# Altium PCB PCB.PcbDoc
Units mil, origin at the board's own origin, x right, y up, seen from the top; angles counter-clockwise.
Board outline 3800 x 1700 mil, 2 copper layers (Top Layer, Bottom Layer), stack 62 mil thick; 48 components, 27 nets, 123 pads, 20 vias.
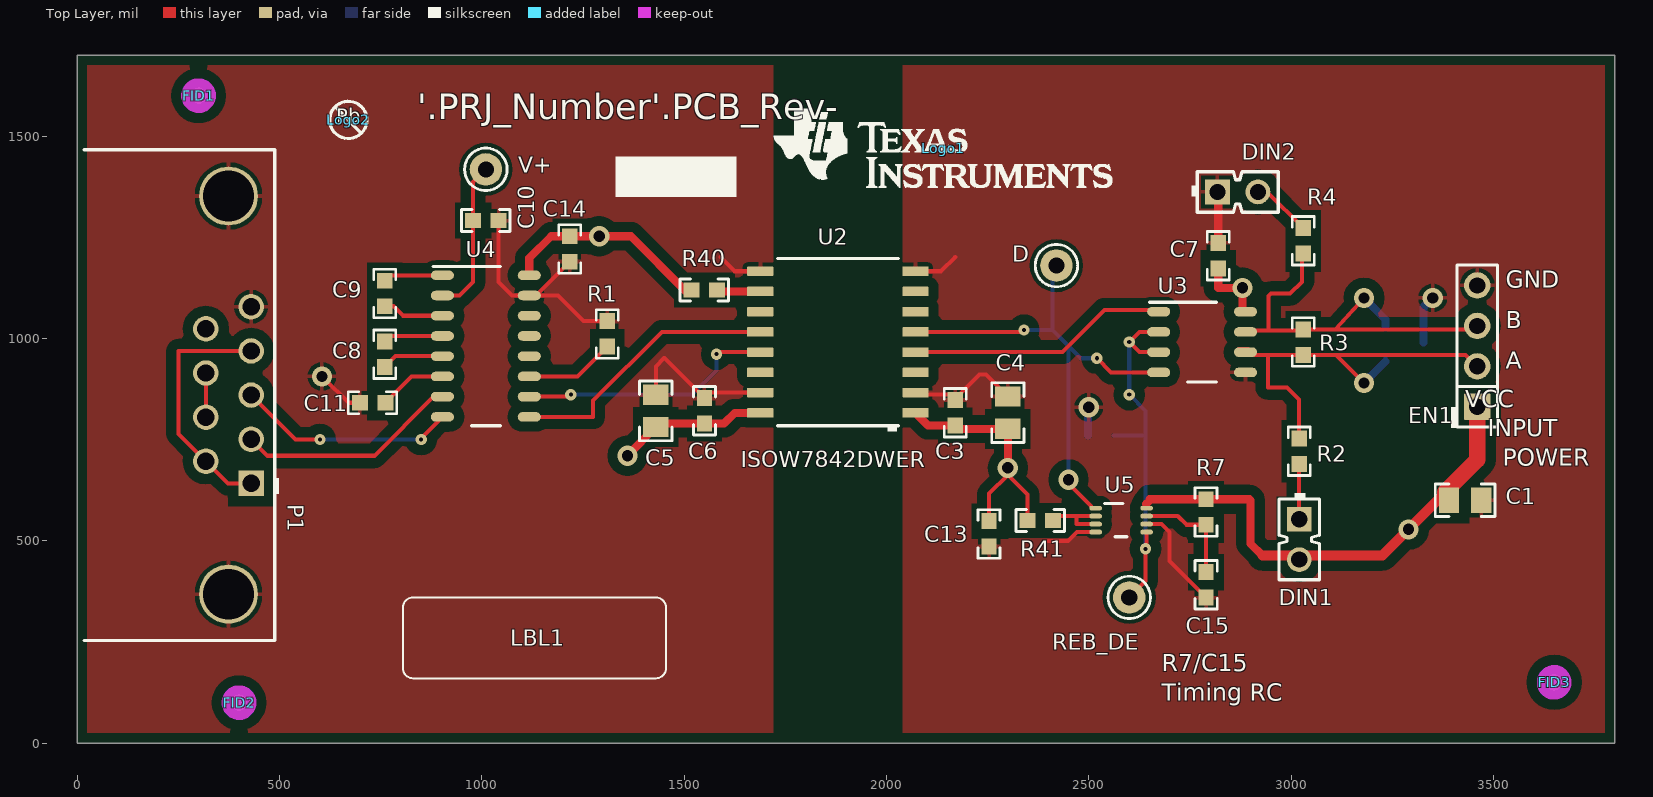
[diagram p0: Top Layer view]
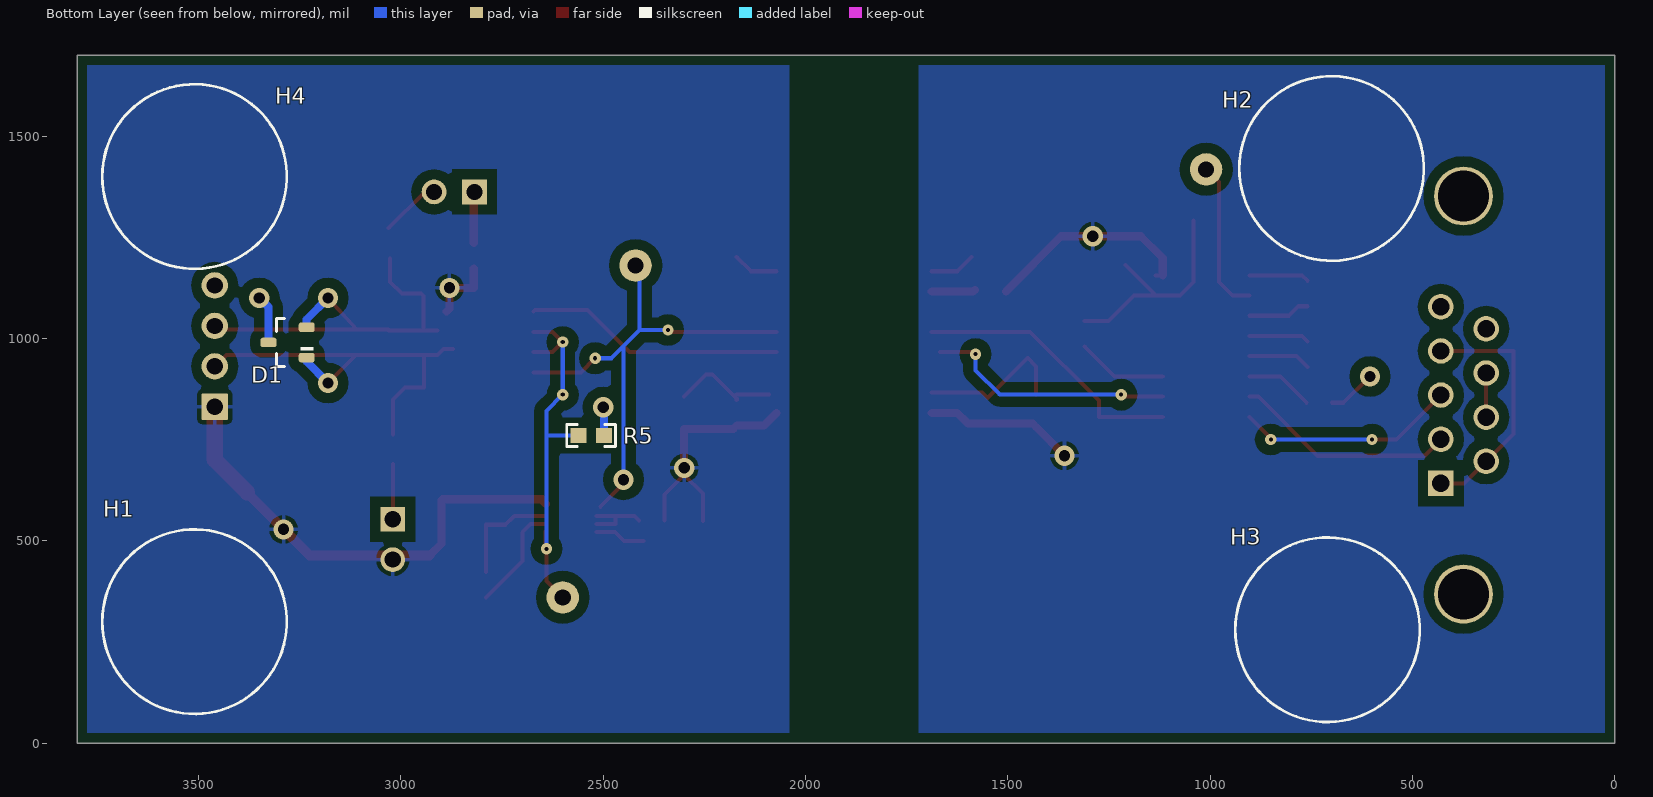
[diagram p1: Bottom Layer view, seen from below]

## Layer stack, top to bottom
Top Solder: solder mask 0.4, Solder Resist, Dk 3.5
Top Layer: signal copper 1.4
Dielectric1: core 59.2, FR-4, Dk 4.8
Bottom Layer: signal copper 1.4
Bottom Solder: solder mask 0.4, Solder Resist, Dk 3.5

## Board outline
0,0 3800,0 3800,1700 0,1700

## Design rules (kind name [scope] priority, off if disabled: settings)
AcuteAngle [All] p1: minimum=4.50000000000000E+0001 checktracksonly=FALSE
AssemblyTestPointUsage [All] p1: valid=2
BoardOutlineClearance BoardOutlineClearance_MountingHoles [OnCopper and InComponentClass('Mounting Holes')] p1: gap=40 ignorepadtopadclearanceinfootprint=FALSE
BoardOutlineClearance BoardOutlineClearance_Poly [OnCopper and IsPoly] p2: gap=25 ignorepadtopadclearanceinfootprint=FALSE
BoardOutlineClearance [OnCopper and Not InComponentClass('Logo') and not InComponentClass('FiducialMark') and not InRegion(1000,500,4000,800) and not InPoly] p3: gap=75 ignorepadtopadclearanceinfootprint=FALSE
Clearance Clearance_Keepouts [((IsTrack Or IsArc) And Not InPoly) And IsFree and IsKeepOut vs ((IsTrack Or IsArc) And Not InPoly) And IsFree and IsKeepOut] p1: gap=0 ignorepadtopadclearanceinfootprint=FALSE
Clearance Clearance_Poly [InPolygon] p2: gap=25 ignorepadtopadclearanceinfootprint=FALSE except(0: Arc-Hole Track-Hole SMDPad-Hole THPad-Hole Via-Hole Fill-Hole Poly-Hole Region-Hole Text-Hole)
Clearance Clearance_FiducialMark [IsKeepOut and InComponentClass('FiducialMark') vs IsPad and InComponentClass('FiducialMark')] p3: gap=0 ignorepadtopadclearanceinfootprint=FALSE
Clearance [All] p4: gap=7.87 ignorepadtopadclearanceinfootprint=FALSE except(0: Arc-Hole Track-Hole SMDPad-Hole THPad-Hole Via-Hole Fill-Hole Poly-Hole Region-Hole Text-Hole)
ComponentClearance ComponentClearance_MountingHoles_FiducialMarks [InComponentClass('Mounting Holes') vs InComponentClass('FiducialMark')] p1: gap=50 collisioncheckmode=3 verticalgap=10 showdistances=FALSE
ComponentClearance ComponentClearance_Shunt [InComponentClass('Header') vs InComponentClass('Shunt')] p2: gap=0 collisioncheckmode=3 verticalgap=0 showdistances=FALSE
ComponentClearance ComponentClearance_Logo [InComponentClass('Logo')] p3: gap=50 collisioncheckmode=3 verticalgap=10 showdistances=FALSE
ComponentClearance ComponentClearance_ScrewToNut [(HasFootprint('NY PMS 440 0025 PH')) vs (HasFootprint('Keystone_1902C'))] p4: gap=5 collisioncheckmode=3 verticalgap=10 showdistances=FALSE
ComponentClearance ComponentClearance_MountingHoles [InComponentClass('Mounting Holes')] p5: gap=250 collisioncheckmode=3 verticalgap=100000 showdistances=FALSE
ComponentClearance ComponentClearance_SmallPassives [HasFootprint('0201*') or HasFootprint('0402*') or HasFootprint('0508') or HasFootprint('0603*') or HasFootprint('0612') or HasFootprint('0805*') or HasFootprint('0815*') or HasFootprint('0830*') or HasFootprint('1206*') or HasFootprint('1210*') or HasFootprint('1808*') or HasFootprint('1812*') or HasFootprint('1825*') or HasFootprint('2010*') or HasFootprint('2220*') or HasFootprint('2225*') or HasFootprint('2512*') or HasFootprint('2728*') or HasFootprint('3518*') vs HasFootprint('0201*') or HasFootprint('0402*') or HasFootprint('0508') or HasFootprint('0603*') or HasFootprint('0612') or HasFootprint('0805*') or HasFootprint('0815*') or HasFootprint('0830*') or HasFootprint('1206*') or HasFootprint('1210*') or HasFootprint('1808*') or HasFootprint('1812*') or HasFootprint('1825*') or HasFootprint('2010*') or HasFootprint('2220*') or HasFootprint('2225*') or HasFootprint('2512*') or HasFootprint('2728*') or HasFootprint('3518*')] p6: gap=14.96 collisioncheckmode=3 verticalgap=10 showdistances=FALSE
ComponentClearance ComponentClearance_THtoSMT [IsThruComponent vs IsSMTComponent] p7: gap=40 collisioncheckmode=3 verticalgap=30 showdistances=FALSE
ComponentClearance ComponentClearance_THtoTH [IsThruComponent vs IsThruComponent] p8: gap=30 collisioncheckmode=3 verticalgap=30 showdistances=FALSE
ComponentClearance [All] p9: gap=30 collisioncheckmode=3 verticalgap=10 showdistances=FALSE
DiffPairsRouting [All] p1: maxlimit=100 minlimit=10 mostfreqgap=10 toplayer_minwidth=15 toplayer_maxwidth=15 toplayer_prefwidth=15 bottomlayer_minwidth=15 bottomlayer_maxwidth=15 bottomlayer_prefwidth=15 maxuncoupledlength=1000
FabricationTestPointUsage TestPointUsage [All] p1: valid=2 allowmultiple=FALSE
FabricationTestpoint Testpoint [All] p1: side=3 testpointundercomponent=TRUE minsize=40 maxsize=100 preferedsize=60 minholesize=0 maxholesize=40 preferedholesize=32 testpointgrid=1 allowsidetop=TRUE allowsidebottom=TRUE usegrid=TRUE gridtolerance=0.01
FanoutControl Fanout_LCC [IsLCC] p1: bgadir=Out bgaviamode=Centered fanoutstyle=Auto fanoutdirection=Alternating viagrid=1 // Fanout_LCC (Default Rule)
FanoutControl Fanout_BGA [IsBGA] p2: bgadir=Out bgaviamode=Centered fanoutstyle=Auto fanoutdirection=Alternating viagrid=1 // Fanout_BGA (Default Rule)
FanoutControl Fanout_Default [All] p4: bgadir=Out bgaviamode=Centered fanoutstyle=Auto fanoutdirection=Alternating viagrid=1 // Fanout_Default (Default Rule)
FanoutControl Fanout_Small [(CompPinCount < 5)] p5: bgadir=Out bgaviamode=Centered fanoutstyle=Auto fanoutdirection=OutThenIn viagrid=1 // Fanout_Small (Default Rule)
HoleSize [All] p1: absolutevalues=TRUE maxlimit=251 minlimit=7.87 maxpercent=80.000 minpercent=20.000
MinimumAnnularRing MinimumAnnularRing_ThermalPadVias [IsVia and InAnyComponent] p1: minimumring=5.91
MinimumAnnularRing [All] p2: minimumring=8
MinimumSolderMaskSliver MinimumSolderMaskSliver_Logo [InComponentClass('Logo') vs InComponentClass('Logo')] p1: minsoldermaskwidth=0.7
MinimumSolderMaskSliver [All] p2: minsoldermaskwidth=3.94
PlaneConnect [All] p1: planeconnectstyle=Relief reliefexpansion=10 reliefentries=4 reliefconductorwidth=10 reliefairgap=10
PolygonConnect [All] p1: connectstyle=Relief reliefconductorwidth=10 reliefentries=4 polygonreliefangle="90 Angle" airgapwidth=10
RoutingVias ThermalPadVias [IsVia and InAnyComponent] p1: holewidth=7.87 width=19.68 viastyle="Through Hole" minholewidth=7.87 minwidth=19.68 maxholewidth=12.99 maxwidth=23.62
RoutingVias [All] p2: holewidth=16 width=34 viastyle="Through Hole" minholewidth=7.87 minwidth=26 maxholewidth=40 maxwidth=65
SilkToBoardRegionClearance [Not ((IsComment or IsDesignator) And (Hide <> 'False')) and not InRegion(1000,500,4000,800)] p1:
SilkToSilkClearance SilkToSilkClearance_Pb-FreeLogo [(HasFootprint('Pb-Free_Overlay_Medium') OR HasFootprint('Pb-Free_Overlay_Small')) vs (HasFootprint('Pb-Free_Overlay_Medium') OR HasFootprint('Pb-Free_Overlay_Small'))] p1: silktosilkclearance=0
SilkToSilkClearance [All] p2: silktosilkclearance=4
SilkToSolderMaskClearance SilkToComponentPadClearance [(IsPad or IsFill or IsRegion) and InAnycomponent] p1: minsilkscreentomaskgap=5 clearancetoexposedcopper=TRUE
SilkToSolderMaskClearance "Silk to Solder Mask Opening" [All] p2: minsilkscreentomaskgap=4 clearancetoexposedcopper=FALSE
SolderMaskExpansion [All] p1: expansion=1.97
Width [All] p1: maxlimit=100 minlimit=6 preferedwidth=10 checkconnectedcopper=TRUE
15 further rules are at their usual default settings.

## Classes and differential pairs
component class Label: LBL1
component class AssemblyNote: ZZ1 ZZ2 ZZ3 ZZ4
component class FiducialMark: FID1 FID2 FID3
component class EVM_Hardware: FID1 FID2 FID3 H1 H2 H3 H4 LBL1 Logo1 Logo2 Logo3 ZZ1 ZZ2 ZZ3 ZZ4
component class Logo: Logo1
component class Header: DIN1 DIN2 EN1

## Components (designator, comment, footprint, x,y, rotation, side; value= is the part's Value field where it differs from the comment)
C1 "EMK212BJ106KG-T" 0805_HV 3430,600 r0 top value=10uF
C3 "GCM188R71C104KA37J" 0603 2170,816.59 r90 top value=0.1uF
C4 "GRM21BC80J106KE19L" 0805_HV 2300,816.59 r90 top value=10uF
C5 "GRM21BC80J106KE19L" 0805_HV 1430,821.04 r90 top value=10uF
C6 "GCM188R71C104KA37J" 0603 1550,821.04 r90 top value=0.1uF
C7 "GCM188R71C104KA37J" 0603 2820,1204.48 r90 top value=0.1uF
C8 "GCM188R71C104KA37J" 0603 760,961.04 r270 top value=0.1uF
C9 "GCM188R71C104KA37J" 0603 760,1111.04 r270 top value=0.1uF
C10 "GCM188R71C104KA37J" 0603 1010,1291.04 r0 top value=0.1uF
C11 "GCM188R71C104KA37J" 0603 730,841.04 r180 top value=0.1uF
C13 "GCM188R71C104KA37J" 0603 2253.7,516.81 r90 top value=0.1uF
C14 "GCM188R71C104KA37J" 0603 1217.36,1221.04 r270 top value=0.1uF
C15 "GRM188R70J224KA88D" 0603 2790,391.04 r270 top value=0.22uF
D "5000" Keystone5000 2420,1180 r90 top
D1 "SM712.TCT" SOT-23 3280,990 r0 bottom value="7V, 12V"
DIN1 "TSW-102-07-T-S" Samtec_TSW-102-07-T-S 3020,503.37 r270 top
DIN2 "TSW-102-07-T-S" Samtec_TSW-102-07-T-S 2867.99,1361.97 r0 top
EN1 "TSW-104-07-G-S" TSW-104-07-G-S 3460,981.04 r90 top
FID1 "Fiducial" Fiducial10-20 300,1600 r0 top
FID2 "Fiducial" Fiducial10-20 400,100 r0 top
FID3 "Fiducial" Fiducial10-20 3650,150 r0 top
H1 "SJ-5303 (CLEAR)" Bumpon_SJ5003Transparent 3510,300 r90 bottom
H2 "SJ-5303 (CLEAR)" Bumpon_SJ5003Transparent 700,1420 r180 bottom
H3 "SJ-5303 (CLEAR)" Bumpon_SJ5003Transparent 710,280 r90 bottom
H4 "SJ-5303 (CLEAR)" Bumpon_SJ5003Transparent 3510,1400 r90 bottom
LBL1 "THT-14-423-10" Label_650x200 1130,260 r0 top
Logo1 "Texas Instruments" TI_Stacked_Overlay_Small 2140,1470 r0 top
Logo2 "Pb-Free Symbol" Pb-Free_Overlay_Small 670,1540 r0 top
Logo3 "FCC disclaimer" FCC_disclaimer 2350,3380 r0 top
P1 "1734354-1" TE_1734354-1 0,860 r180 top
R1 "ERJ-3GEYJ472V" 0603 1310,1011.04 r90 top value=4.7k
R2 "ERJ-3GEYJ472V" 0603 3020,721.04 r270 top value=4.7k
R3 "CRCW0603120RJNEA" 0603 3030,991.04 r270 top value=120
R4 "ERJ-3GEYJ472V" 0603 3030,1241.04 r270 top value=4.7k
R5 "ERJ-3GEYJ472V" 0603 2530,760 r0 bottom value=4.7k
R7 "RMCF0603FT10K0" 0603 2790,571.04 r90 top value=10.0k
R40 "ERJ-3GEYJ472V" 0603 1550,1120 r180 top value=4.7k
R41 "ERJ-3GEYJ472V" 0603 2380,550 r180 top value=4.7k
REB_DE "5000" Keystone5000 2600,360 r90 top
U2 "ISOW7842DWER" DWE0016A 1880,991.04 r180 top
U3 "THVD1410D" D0008A_N 2780,991.04 r0 top
U4 "TRS3232EID" D0016A_N 1010,981.04 r0 top
U5 "SN74LVC1G123DCUR" DCU0008A_N 2580,551.04 r0 top
V+ "5000" Keystone5000 1010,1417.81 r90 top
ZZ1 "These assemblies must comply with workmanship standards IPC-A-610 Class 2, unless otherwise specified." AssemblyNote 185,3652 r0 top
ZZ2 "These assemblies must be clean and free from flux and all contaminants. Use of no clean flux is not acceptable." AssemblyNote 185,3740.56 r0 top
ZZ3 "These assemblies are ESD sensitive, ESD precautions shall be observed." AssemblyNote 185,3829.11 r0 top
ZZ4 "This Assembly Note is for PCB labels only" AssemblyNoteLabel 185,3938 r0 top

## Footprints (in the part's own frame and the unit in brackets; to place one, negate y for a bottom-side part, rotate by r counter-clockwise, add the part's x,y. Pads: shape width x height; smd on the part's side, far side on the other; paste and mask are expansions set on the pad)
0603 [mm] "0603 from SM-752 data"
  rect 1x0.95 smd: 1(-0.8,0) 2(0.8,0)
  silkscreen extent -1.52,-0.69 1.52,0.69, body extent -0.87,-0.47 0.87,0.47, height 1
0805_HV [mil] "0805 with 30mil clearance between pads"
  rect 50x63 smd: 1(-40,0) 2(40,0)
  silkscreen extent -74,-40 74,40, body extent -43,-29 43,29, height 57
AssemblyNote [mil] "Assembly Note"
AssemblyNoteLabel [mil] "Assembly Note for PCB Labels"
Bumpon_SJ5003Transparent [mil] "3M Hemispherical Bumpon transparent"
  round 1 on Mech4: 0(0,0)
  silkscreen extent -228,-228 228,228, body extent -219,-219 219,219, height 197
D0008A_N [mm] "SOIC, 8-Leads, Body 4.9x3.9mm, Pitch 1.27mm, IPC Medium Density"
  oval 1.45x0.6 smd: 1(-2.725,1.905) 2(-2.725,0.635) 3(-2.725,-0.635) 4(-2.725,-1.905) 5(2.725,-1.905) 6(2.725,-0.635) 7(2.725,0.635) 8(2.725,1.905)
  silkscreen extent -3.3,-2.5 0.9,2.5, body extent -3,-2.45 3,2.45, height 1.63
D0016A_N [mm] "SOIC, 16-Leads, Body 9.9x3.9mm, Pitch 1.27mm, IPC Medium Density"
  oval 1.45x0.6 smd: 1(-2.725,4.445) 2(-2.725,3.175) 3(-2.725,1.905) 4(-2.725,0.635) 5(-2.725,-0.635) 6(-2.725,-1.905) 7(-2.725,-3.175) 8(-2.725,-4.445) 9(2.725,-4.445) 10(2.725,-3.175) 11(2.725,-1.905) 12(2.725,-0.635) 13(2.725,0.635) 14(2.725,1.905) 15(2.725,3.175) 16(2.725,4.445)
  silkscreen extent -3.3,-5 0.9,5, body extent -3,-4.95 3,4.95, height 1.6
DCU0008A_N [mm] "TSSOP, 8-Leads, Body 2x2.3mm, Pitch 0.5mm, IPC Medium Density"
  oval 0.8x0.3 smd: 1(-1.6,0.75) 2(-1.6,0.25) 3(-1.6,-0.25) 4(-1.6,-0.75) 5(1.6,-0.75) 6(1.6,-0.25) 7(1.6,0.25) 8(1.6,0.75)
  silkscreen extent -1.05,-1.05 0.38,1.05, body extent -1.56,-1 1.56,1, height 0.9
DWE0016A [mm] "SOIC, 16-Leads, Body 10.5x7.6mm, Pitch 1.27mm"
  rrect17% 1.65x0.6 smd: 1(-4.875,4.445) 2(-4.875,3.175) 3(-4.875,1.905) 4(-4.875,0.635) 5(-4.875,-0.635) 6(-4.875,-1.905) 7(-4.875,-3.175) 8(-4.875,-4.445) 9(4.875,-4.445) 10(4.875,-3.175) 11(4.875,-1.905) 12(4.875,-0.635) 13(4.875,0.635) 14(4.875,1.905) 15(4.875,3.175) 16(4.875,4.445)
  silkscreen extent -3.8,-5.25 3.8,5.6, body extent -5.17,-5.15 5.17,5.15, height 2.59
FCC_disclaimer [mil]
Fiducial10-20 [mm]
  round 1 smd mask+0.5: 1(0,0)
  Top Layer keep-out circle w1.178: c0,0 r0.5
Keystone5000 [mil] "For Keystone 500x miniature loop terminals"
  round 80 hole 40: 1(0,0)
  silkscreen extent -52,-52 52,52, body extent -49,-49 49,49, height 182
Label_650x200 [mil] "Thermal Transfer Label"
  round 1 on Mech13: 0(0,0)
  silkscreen extent -325,-100 325,100, body extent -325,-100 325,100, height 1
Pb-Free_Overlay_Small [mil]
  silkscreen extent -46,-46 46,46
Samtec_TSW-102-07-T-S [mm] "Header, 2.54 mm, 2x1, Tin, TH"
  rect 1.55x1.55 hole 1.02: 1(-1.27,0)
  round 1.55 hole 1.02: 2(1.27,0)
  silkscreen extent -2.9,-1.27 2.54,1.27, body extent -2.54,-1.27 2.54,1.27, height 8.38
SOT-23 [mm] "SOT23, 3-Leads, Body 2.9x1.3mm, Pitch 0.95mm, Lead Span 2.5mm, IPC Medium Density"
  rrect50% 1x0.6 smd: 1(-1.2,0.95) 2(-1.2,-0.95) 3(1.2,0)
  silkscreen extent -1.62,-1.5 0.7,1.5, body extent -1.16,-1.45 1.21,1.45, height 1
TE_1734354-1 [mm] "Receptacle, D-Sub, 9 Position, R/A, TH"
  rect 1.6x1.6 hole 1.09: 1(-10.92,5.54)
  round 1.6 hole 1.09: 2(-10.92,2.77) 3(-10.92,0) 4(-10.92,-2.77) 5(-10.92,-5.54) 6(-8.08,4.155) 7(-8.08,1.385) 8(-8.08,-1.385) 9(-8.08,-4.155)
  round 3.7 hole 3.18: 10(-9.5,12.495) 11(-9.5,-12.495)
  silkscreen extent -12.68,-15.4 -0.43,15.4, body extent -12.4,-15.4 6.02,15.4, height 12.5
TI_Stacked_Overlay_Small [mil]
  silkscreen extent -418,-98 418,98
TSW-104-07-G-S [mm] "Samtec 100mil, 1x4, 230 mil above insulator"
  rrect6% 1.65x1.65 hole 1.016: 1(-3.81,0)
  round 1.65 hole 1.016: 2(-1.27,0) 3(1.27,0) 4(3.81,0)
  silkscreen extent -5.16,-1.27 5.08,1.65, body extent -5.08,-1.27 5.08,1.27, height 8.38

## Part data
C1: "CAP, CERM, 10 µF, 16 V,+/- 10%, X5R, 0805", Cap_Case=0805, Manufacturer="Taiyo Yuden", Supplier Part Number 1=587-1295-1-ND, TempCo=X5R, Tolerance_%=10, Value2=16V, ValueDisplayed=10µF
C3 C6 C7 C13: "CAP, CERM, 0.1 µF, 16 V,+/- 10%, X7R, AEC-Q200 Grade 1, 0603", Cap_Case=0603, Manufacturer=MuRata, Supplier Part Number 1=490-8015-1-ND, TempCo=X7R, Tolerance_%=10, Value2=16V, ValueDisplayed=0.1µF
C4 C5: "CAP, CERM, 10 µF, 6.3 V,+/- 10%, X6S, 0805", Cap_Case=0805, Manufacturer=MuRata, Supplier Part Number 1=GRM21BC80J106KE19L-ND, TempCo=X6S, Tolerance_%=10, Value2=6.3V, ValueDisplayed=10µF
C8 C9 C10 C11 C14: "CAP, CERM, 0.1 µF, 16 V, +/- 10%, X7R, AEC-Q200 Grade 1, 0603", Cap_Case=0603, Manufacturer=MuRata, Supplier Part Number 1=490-8015-1-ND, TempCo=X7R, Tolerance_%=10, Value1=Unknown, Value2=16V, ValueDisplayed=0.1µF
C15: "CAP, CERM, 0.22 µF, 6.3 V,+/- 10%, X7R, 0603", Cap_Case=0603, Manufacturer=MuRata, Supplier Part Number 1=GRM188R70J224KA88D-ND, TempCo=X7R, Tolerance_%=10, Value2=6.3V, ValueDisplayed=0.22µF
D REB_DE V+: "Test Point, Miniature, Red, TH", Color=Red, Manufacturer=Keystone, Supplier Part Number 1=36-5000-ND
D1: "Asymmetrical TVS Diode for Extended Common-Mode RS-485, SOT-23", Manufacturer=Semtech, Supplier Part Number 1=SM712CT-ND
DIN1 DIN2: "Header, 2.54 mm, 2x1, Tin, TH", Color=Black, Current_A=6.3, Manufacturer=Samtec, Supplier Part Number 1=SAM1035-02-ND, Voltage_V=550
EN1: "Header, 100mil, 4x1, Gold, TH", Color=Black, Current_A=6.3, Manufacturer=Samtec, Supplier Part Number 1=SAM1029-04-ND, Voltage_V=550
FID1 FID2 FID3: library part CMP-0077181-1, "Fiducial mark.  There is nothing to buy or mount.", Manufacturer=N/A
H1 H2 H3 H4: library part CMP-0003620-1, "Bumpon, Hemisphere, 0.44 X 0.20, Clear", Manufacturer=3M, Supplier Part Number 1=SJ5303-7-ND
LBL1: library part CMP-0003625-1, "Thermal Transfer Printable Labels, 0.650\" W x 0.200\" H - 10,000 per roll", Manufacturer=Brady, Supplier Part Number 1=97C5133
Logo1: library part CMP-0074838-1, "Texas Instrument Corporate Signature"
Logo2: library part CMP-0074839-1
Logo3: library part CMP-0074847-1, "FCC_disclaimer"
P1: "Receptacle, D-Sub, 9 Position, R/A, TH", Color=Black, Manufacturer="TE Connectivity", Supplier Part Number 1=A35107-ND
R1 R2 R4 R5 R40 R41: "RES, 4.7 k, 5%, 0.1 W, AEC-Q200 Grade 0, 0603", Manufacturer=Panasonic, Power_W=0.1, Supplier Part Number 1=P4.7KGCT-ND, TempCo="200 ppm/C", Tolerance_%=5, Value1=5%, Value2=0.1W, Value_Code=4k70, ValueDisplayed=4.7k
R3: "RES, 120, 5%, 0.1 W, 0603", Manufacturer=Vishay-Dale, Power_W=0.1, Supplier Part Number 1=541-120GCT-ND, TempCo="200 ppm/C", Tolerance_%=5, Value1=5%, Value2=0.1W, Value_Code=120R, ValueDisplayed=120
R7: "RES, 10.0 k, 1%, 0.1 W, AEC-Q200 Grade 0, 0603", Manufacturer="Stackpole Electronics Inc", Power_W=0.1, Supplier Part Number 1=RMCF0603FT10K0CT-ND, TempCo="100 ppm/C", Tolerance_%=1, Value1=1%, Value2=0.1W, Value_Code=10k0, ValueDisplayed=10.0k
U2: "High-Performance, 5000-VRMS Reinforced Quad-Channel Digital Isolators With Integrated High-Efficiency, Low-Emissions DC-DC Converter, DWE0016A (SOIC-16)", Alternate Manufacturer="Texas Instruments", Alternate PartNumber=ISOW7842DWE
U3: library part CMP-0065060-3, "3.3-V to 5-V RS-485 Transceivers With +/-18-kV IEC ESD Protection, D0008A (SOIC-8)", Alternate Manufacturer="Texas Instruments", Alternate PartNumber=THVD1410DR, Operating Temperature Range="-40 to 125 C"
U4: "3-V to 5.5-V Multichannel RS-232 Line Driver / Receiver with ±15-kV IEC ESD Protection, -40 to 85 degC, 16-Pin SOIC (D), Green (RoHS & no Sb/Br)", Alternate Manufacturer="Texas Instruments", Alternate PartNumber=Equivalent, Drivers Per Package=2, Supplier Part Number 1=TRS3232EID-ND, Supply Voltage(s)(V)="3.3 or 5.0"
U5: "Single Retriggerable Monostable Multivibrator with Schmitt-Trigger Inputs, DCU0008A, LARGE T&R", Alternate Manufacturer="Texas Instruments", Alternate PartNumber=Equivalent, F @ Nom Voltage(Max)(Mhz)=150, Generic Part Number=SN74LVC1G123, ICC @ Nom Voltage(Max)(mA)=0.02, Operating Temperature Range(C)="-40 to 125,-40 to 85", Rating=Catalog, Supplier Part Number 1=595-SN74LVC1G123DCUR, tpd @ Nom Voltage(Max)(ns)=34,11,8,5.5, Voltage(Nom)(V)=1.8,2.5,3.3,5
ZZ1: library part CMP-0077238-1
ZZ2: library part CMP-0077237-1
ZZ3: library part CMP-0077236-1
ZZ4: library part CMP-0003616-3

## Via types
v1: diameter 50, hole 28, Top Layer to Bottom Layer, 11 vias
v2: diameter 28, hole 10, Top Layer to Bottom Layer, 9 vias

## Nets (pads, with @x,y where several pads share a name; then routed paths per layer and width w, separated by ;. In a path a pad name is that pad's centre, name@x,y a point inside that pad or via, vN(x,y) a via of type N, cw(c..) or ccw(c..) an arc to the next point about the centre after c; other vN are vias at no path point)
A: D1.1 EN1.2 R2.1 R3.2 U3.6 | length 1047.2
  Top Layer w10: U3.6@2871.46,974.38 2894.32,974.38 2909.16,959.54 2944.21,959.54 ; R2.1@3020,762.53 3020,848.7 2990,878.7 2942.34,878.7 2942.34,957.67 2944.21,959.54 ; v1(3180,890) 3110.46,959.54 ; EN1.2 3431.5,959.54 3110.46,959.54 ; 2944.21,959.54 R3.2 3110.46,959.54
  Bottom Layer w10: D1.1@3232.76,942.76 D1.1
  Bottom Layer w20: v1(3180,890) D1.1@3232.76,942.76
B: D1.2 EN1.3 R3.1 R4.2 U3.7 | length 1000.2
  Top Layer w10: U3.7@2909.16,1019.54 2944.21,1019.54 ; R4.2@3026.51,1197.04 3026.51,1139.88 2997.66,1111.04 2950,1111.04 2944.21,1105.25 2944.21,1019.54 ; R3.1@3030,1019.54 2944.21,1019.54 ; R3.1 3110,1022.53 ; v1@3180,1092.53 v1(3180,1100) 3110,1022.53 ; EN1.3 3451.5,1022.53 3110,1022.53
  Bottom Layer w20: v1(3180,1100) 3232.76,1047.24 D1.2
D: D.1 U2.5 U3.4 U5.1 | length 1222.4
  Top Layer w10: U2.5 2335,1016.04 v2(2340,1021) ; v1@2450,641.04 U5.1@2507.01,584.03 ; v2@2521.61,952.65 v2(2520,951.04) 2555,916.04 U3.4
  Bottom Layer w10: v2(2340,1021) 2410,1021.04 ; D.1 2410,1170 2410,1021.04 ; v1(2450,651) 2450,981.04 ; v2(2520,951.04) 2480,951.04 2450,981.04 ; 2410,1021.04 2450,981.04
DIN: U2.13 U4.10 | length 619.8
  Top Layer w10: U4.10 1215,856.04 v2(1220,861.04) ; v2(1580,961.04) 1585,966.04 U2.13@1668.07,966.04
  Bottom Layer w10: v2(1220,861.04) 1520,861.04 1580,921.04 v2(1580,961.04)
GND: C5.2 C6.2 C10.2 C11.2 C14.2 P1.5 P1.10 P1.11 R1.2 U2.9 U2.15 U4.15 | length 1174.9
  Top Layer w10: v1@610,901.04 670,841.04 C11.2 ; C10.2 1041.5,1139.54 1075,1106.04 U4.15 U4.15@1133.86,1106.04 ; C14.2@1208.86,1181.04 U4.15@1133.86,1106.04 ; R1.2 1251.5,1042.53 1230,1064.03 1187.99,1106.04 U4.15@1133.86,1106.04 ; C5.2 1430,931.04 1450,951.04 1451.5,951.04 C6.2 1563.5,866.04 U2.15 ; 1590,1201.04 1625,1166.04 U2.9
  other v1: 605,906.04
GND_SIGNAL: C1.2 C3.2 C4.2 C7.2 C13.1 C15.2 D1.3 DIN2.1 EN1.4 R5.1 U2.2 U2.8 U3.5 U5.4 U5.6 | length 1080.2
  Top Layer w10: U2.8 2135,1166.04 2170,1201.04 ; U2.2@2090,861.04 C3.2@2170.12,861.04 ; C3.2 2170,851.04 2230,911.04 2245.55,911.04 C4.2 ; 2400,499.54 2448.5,499.54 2470.47,521.51 U5.4 ; U5.6 2679.84,541.2 2700,521.04 2700,449.54 C15.2
  Top Layer w20: DIN2.1 2820,1359.97 C7.2
  Bottom Layer w20: R5.1 2498.5,828.5 v1(2500,830) ; D1.3 3327.24,1077.24 v1(3350,1100)
NetC8_1: C8.1 U4.4 | length 148.3
  Top Layer w10: C8.1 773.5,1006.04 U4.4
NetC8_2: C8.2 U4.5 | length 153.7
  Top Layer w10: C8.2 786.5,956.04 U4.5
NetC9_1: C9.1 U4.1 | length 148.3
  Top Layer w10: C9.1 773.5,1156.04 U4.1
NetC9_2: C9.2 U4.3 | length 152.5
  Top Layer w10: C9.2 781.5,1079.54 805,1056.04 U4.3
NetC10_1: C10.1 U4.2 V+.1 | length 381
  Top Layer w10: U4.2 945,1106.04 978.5,1139.54 C10.1 978.5,1386.32 V+.1
NetC11_1: C11.1 U4.6 | length 168.1
  Top Layer w10: C11.1 826.5,906.04 U4.6
NetC15_1: C15.1 R7.1 U5.7 | length 272.9
  Top Layer w10: U5.7 2719.84,560.88 2741.18,539.54 R7.1 C15.1
NetDIN1_1: DIN1.1 R2.2 | length 126
  Top Layer w10: DIN1.1@3020,563.55 R2.2
NetDIN2_2: DIN2.2 R4.1 | length 149.1
  Top Layer w10: DIN2.2 2940.56,1361.97 R4.1
NetP1_1: P1.1 P1.4 P1.6 | length 613.8
  Top Layer w10: P1.1 372.64,641.89 P1.6 250.94,763.58 250.94,969.06 P1.4
NetP1_7: P1.7 P1.8 | length 109.1
  Top Layer w10: P1.7 P1.8
NetR1_1: R1.1 U4.11 | length 223.2
  Top Layer w10: U4.11 1236.5,906.04 R1.1
NetR40_1: R40.1 U2.10 | length 108.2
  Top Layer w20: R40.1 1585.46,1116.04 U2.10
NetR41_1: R41.1 U5.2 U5.3 | length 177.2
  Top Layer w10: R41.1 2422.38,560.88 2470,560.88 ; U5.3 2469.69,541.2 2470,541.51 2470,560.88 ; U5.2 2470,560.88
R: U2.4 U3.1 | length 645.5
  Top Layer w10: U2.4 2435,966.04 2538.96,1070 2668.75,1070 U3.1
RD: P1.3 U4.8 | length 520.7
  Top Layer w10: P1.3 529.92,760 530,760 540,750 v2@590,750 ; v2@856.68,760 U4.8
  Bottom Layer w10: v2(600,750) 840,750 v2(850,750)
REB_DE: R5.2 REB_DE.1 U3.2 U3.3 U5.5 | length 952.9
  Top Layer w10: REB_DE.1 2640,400 v2(2640,480) 2642.99,482.99 U5.5 U5.5@2642.09,522.42 ; U3.3 2625,966.04 v2(2600,991.04) 2625,1016.04 U3.2
  Bottom Layer w10: R5.2 2640,760 ; v2(2600,991.04) v2(2600,861.04) 2640,821.04 2640,760 ; v2(2640,480) 2640,760
ROUT: U2.12 U4.9 | length 681.2
  Top Layer w10: U4.9 1275,806.04 1275,846.04 1445,1016.04 U2.12
TD: P1.2 U4.7 | length 550.2
  Top Layer w10: P1.2 470.87,710 735.04,710 881.08,856.04 U4.7
VCC: C1.1 C3.1 C4.1 C7.1 C13.2 DIN1.2 EN1.1 R7.2 R41.2 U2.1 U3.8 U5.8 | length 1965
  Top Layer w10: C3.1 C3.1@2178.5,776.59 ; C13.2 2253.7,616.23 v1@2300,662.53 ; v1@2300,700 v1(2300,680) v1@2300,662.53 ; R41.2 2348.5,614.03 v1@2300,662.53
  Top Layer w20: U2.1 2102.87,785.09 C3.1 ; C3.1@2178.5,776.59 C4.1 v1@2300,700 ; 2641.47,590.41 2648.79,597.74 ; 2650.31,602.53 R7.2 2897.47,602.53 2900,600 2900,492.53 2928.99,463.55 ; C7.1 2820,1124.88 v1(2880,1124.88) 2880,1073.32 U3.8 ; C1.1@3380,618.22 C1.1@3380,620
  Top Layer w25: 2928.99,463.55 3225.32,463.55 C1.1@3380,618.22
  Top Layer w40: C1.1@3380,620 3460,700 EN1.1
  other v1: 3290,528
VSIO: C5.1 C6.1 C14.1 R40.2 U2.16 U4.16 | length 887.3
  Top Layer w10: U4.16 U4.16@1135,1156.04 ; v1(1360,710) v1@1360,711.04
  Top Layer w20: U4.16 1117.28,1198.32 1171.5,1252.53 C14.1 1368.5,1252.53 R40.2@1505,1116.04 ; v1@1360,711.04 C5.1 ; C5.1@1438.5,789.54 C6.1 1598.5,789.54 1625,816.04 U2.16
  other v1: 1290,1252.53
pads on no net: FID1.1 FID2.1 FID3.1 H1.0 H2.0 H3.0 H4.0 LBL1.0 P1.9 U2.3 U2.6 U2.7 U2.11 U2.14 U4.12 U4.13 U4.14

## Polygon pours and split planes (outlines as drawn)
GND_SIGNAL on Top Layer "TOP_LAYER_GND_SIGNAL_P006" (solid, remove dead copper, pour order 6): 2040,0 2040,1700 3800,1700 3800,0
GND on Top Layer "TOP_LAYER_GND_P004" (solid, remove dead copper, pour order 4): 0,1690 10,1700 1720,1700 1720,0 0,0
VSIO on Bottom Layer "BOTTOM_LAYER_VSIO_P008" (solid, remove dead copper, pour order 8): 0,0 0,1700 1720,1700 1720,0
VCC on Bottom Layer "BOTTOM_LAYER_VCC_P010" (solid, remove dead copper, pour order 10): 2040,0 2040,1700 3800,1700 3800,0

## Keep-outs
Keep-Out Layer:
  text ".Layer_Name" at 577,-858.49 h60

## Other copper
Top Layer:
  text ".Layer_Name" at 577,-858.49 h60
Bottom Layer:
  text ".Layer_Name" at 577,-858.49 h60

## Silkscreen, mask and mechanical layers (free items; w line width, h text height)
Top Overlay:
  region: 1630,1450 1330,1450 1330,1350 1630,1350
  text "'.PRJ_Number'.PCB_Rev-" at 840,1520 h108.27
  text "GND" at 3530,1110 h72.83
  text "B" at 3530,1010 h72.83
  text "A" at 3530,910 h72.83
  text "VCC /    INPUT /      POWER" at 3430,670 h72.83
  text "R7/C15 / Timing RC" at 2680,90 h72.83
  text ".Layer_Name" at 577,-858.49 h60
Bottom Overlay:
  text ".Layer_Name" at 577,-858.49 h60
Top Paste:
  text ".Layer_Name" at 577,-858.49 h60
Bottom Paste:
  text ".Layer_Name" at 577,-858.49 h60
Top Solder:
  text ".Layer_Name" at 577,-858.49 h60
  text ".Layer_Name" at 577,-858.49 h60
Bottom Solder:
  text ".Layer_Name" at 577,-858.49 h60
Drill Guide:
  text ".Layer_Name" at 577,-858.49 h60
M1 Board Outline:
  the board outline again, w10
  text ".Layer_Name" at 577,-858.49 h60
M2 Board Dimensions:
  rectangle: 125,-400 500,-275
  rectangle: 0,-275 125,-150
  lines w7: 0,-275 1000,-275 ; 125,-400 125,-150 ; 250,-400 250,-150 ; 500,-400 500,-150 ; 750,-400 750,-150 ; 0,-400 0,-150 1000,-150 1000,-400 0,-400
  lines w10: -120,60 -100,0 ; -120,1640 -100,1700 ; -110,0 -90,0 ; -110,1700 -90,1700 ; -100,574.08 -100,0 ; -100,1125.92 -100,1700 ; -80,60 -100,0 ; -80,1640 -100,1700
  text "1700 (mil)" at -64.01,584.08 h60 r90
  text ".Layer_Name" at 577,-858.49 h60
M3 3D STEP Top:
  text ".Layer_Name" at 577,-858.49 h60
M4 3D STEP Bottom:
  text ".Layer_Name" at 577,-858.49 h60
M5 Assembly Top:
  lines w10: -292,-930.17 6308,-930.17 ; -292,-726.83 6310,-726.83 ; -292,-523.5 -292,-1133.5 3713,-1133.5 6310,-1133.5 6310,-523.5 -291.5,-523.5 -291.5,-1133.5 1284,-1133.5 ; 2173,-1133.5 2173,-523.5 ; 3440,-726.83 3440,-523.5 ; 4280,-726.83 4280,-523.5 ; 4902,-1140 4902,-937.17
  text "COMPONENTS MARKED 'DNP' SHOULD NOT BE POPULATED." at 1153.5,-318.5 h60
  text "ASSEMBLY VARIANT:" at 1153,-434 h60
  text ".VariantName" at 2189,-434 h60
  text "PCB VIEWED FROM TOP SIDE" at -228.5,-655.67 h60
  text "BOARD #:" at 2248,-655.67 h60
  text ".PRJ_Number" at 2793.5,-655.67 h60
  text "REV:" at 3638,-655.67 h60
  text ".PCB_Rev" at 3929.5,-655.67 h60
  text "SVN REV:" at 4476,-655.67 h60
  text ".VersionControl_RevNumber" at 4982,-655.67 h60
  text "TID #:" at 2248,-859 h60
  text ".TID" at 2793.5,-859 h60
  text "PLOT NAME =" at -228.5,-1064.34 h60
  text ".plot_File_Name" at 577,-1064.34 h60
  text "GENERATED    :" at 2250,-1064.34 h60
  text ".Print_Date" at 3119.5,-1064.34 h60
  text ".Print_Time" at 3848.5,-1064.34 h60
  text "TEXAS INSTRUMENTS" at 5113,-1064.34 h60
M6 Assembly Bottom:
  lines w10: -292.5,-727.33 6309.5,-727.33 ; -290.5,-930.67 6309.5,-930.67 ; 1115.5,-1140.5 1115.5,-937.67 ; 1737.5,-727.33 1737.5,-524 ; 2577.5,-727.33 2577.5,-524 ; 3844.5,-1134 3844.5,-524 ; 4733.5,-1134 6309,-1134 6309,-524 -292.5,-524 -292.5,-1134 2304.5,-1134 6309.5,-1134 6309.5,-524
  text "COMPONENTS MARKED 'DNP' SHOULD NOT BE POPULATED." at 6102,-318 h60
  text ".VariantName" at 5058,-434 h60
  text "ASSEMBLY VARIANT:" at 6097,-434 h60
  text ".VersionControl_RevNumber" at 1035.5,-656.17 h60
  text "SVN REV:" at 1541.5,-656.17 h60
  text ".PCB_Rev" at 2088,-656.17 h60
  text "REV:" at 2379.5,-656.17 h60
  text ".PRJ_Number" at 3224,-656.17 h60
  text "BOARD #:" at 3769.5,-656.17 h60
  text "PCB VIEWED FROM BOTTOM SIDE" at 6246,-656.17 h60
  text ".TID" at 3224,-859.5 h60
  text "TID #:" at 3769.5,-859.5 h60
  text "TEXAS INSTRUMENTS" at 904.5,-1064.84 h60
  text ".Print_Time" at 2169,-1064.84 h60
  text ".Print_Date" at 2898,-1064.84 h60
  text "GENERATED    :" at 3767.5,-1064.84 h60
  text ".plot_File_Name" at 5440.5,-1064.84 h60
  text "PLOT NAME =" at 6246,-1064.84 h60
M9 Title Sheet:
  drawing of 57 lines, arcs and shapes, not listed
  text "1" at 739.84,8036.5 h70
  text "2" at 3235.5,8036.5 h70
  text "3" at 5724.84,8036.5 h70
  text "4" at 8231.51,8036.5 h70
  text "5" at 10730.5,8036.5 h70
  text "6" at 13235.5,8036.5 h70
  text "A" at -416.5,6893.5 h70
  text "A" at 14383.5,6893.5 h70
  text "B" at -416.5,4513.5 h70
  text "B" at 14383.5,4513.5 h70
  text "C" at -416.5,2138.5 h70
  text "C" at 14383.5,2138.5 h70
  text "PROJECT TITLE:" at 11343.5,277.5 h45
  text ".PRJ_Title" at 11393.5,144.17 h70
  text "DESIGNED FOR:" at 11343.5,-23.5 h45
  text ".PRJ_Customer" at 11393.5,-163.5 h70
  text "D" at -416.5,-231.5 h70
  text "D" at 14383.5,-231.5 h70
  text "FILE NAME:" at 11343.5,-323.5 h45
  text ".PCB_File_Name_No_Path" at 11393.5,-443.5 h70
  text "Texas Instruments (TI) and/or its licensors do not warrant the accuracy or completeness of this specification" at 6374,-605.34 h45
  text "ENGINEER:" at 11343.5,-613.5 h45
  text "LAYOUT BY:" at 12848.5,-613.5 h45
  text "or any information contained therein. TI and/or its licensors do not warrant that this design will meet" at 6329.01,-718 h45
  text ".PRJ_Engineer" at 11393.5,-768.49 h70
  text ".PCB_Layout" at 12899,-768.49 h70
  text "the specifications, will be suitable for your application or fit for any particular purpose, or will operate in" at 6329.01,-830.67 h45
  text ".Layer_Name" at 577,-858.49 h60
  text "ALTIUM DESIGNER VERSION:" at 12848.5,-923.5 h45
  text "an implementation. TI and/or its licensors do not warrant that the design is production worthy. You should" at 6329.01,-943.33 h45
  text "completely validate and test your design implementation to confirm the system functionality for your application." at 6374,-1056 h45
  text ".print_Scale" at 11393.5,-1056.83 h70
  text ".Application_BuildNumber" at 12899,-1056.83 h70
  text "1" at 739.84,-1263.5 h70
  text "2" at 3235.5,-1263.5 h70
  text "3" at 5724.84,-1263.5 h70
  text "4" at 8231.51,-1263.5 h70
  text "5" at 10730.5,-1263.5 h70
  text "6" at 13235.5,-1263.5 h70
M10 Fab Notes:
  drawing of 189 lines, arcs and shapes, not listed
  text "DESIGN INFORMATION" at 12382.02,6356.17 h60
  text "MIN. TRACK WIDTH:" at 11737.46,6224.05 h60
  text "8" at 12833.7,6224.05 h60
  text "MIL" at 12988.46,6224.05 h60
  text "MIN. CLEARANCE:" at 11737.46,6099.92 h60
  text "0.2" at 12773.7,6099.93 h60
  text "mm" at 12988.46,6099.92 h60
  text "MIN. VIA PAD SIZE:" at 11737.46,5975.8 h60
  text "24" at 12803.71,5975.8 h60
  text "MIL" at 12988.46,5975.8 h60
  text "0.05mm (2MIL)" at 12432.46,5845.9 h60
  text "MINIMUM ANNULAR RING" at 11408.23,5837.67 h60
  text "EXTERNAL" at 13140.46,5837.67 h60
  text "PER" at 11608.23,5727.55 h60
  text "IPC-D-275 CLASS 2 LEVEL C" at 11828.23,5727.54 h60
  text "MIL, HOLES" at 13316.46,5627.07 h60
  text "+/-" at 12924,5618.48 h60
  text "+/-" at 13778,5618.48 h60
  text "REGISTRATION TOLERANCES:" at 11408.23,5617.42 h60
  text "METAL" at 12608,5617.42 h60
  text "5" at 13184.2,5617.42 h60
  text "3" at 14017.2,5617.42 h60
  text "MIL" at 14133.46,5617.42 h60
  text "HOLE SIZE TOLERANCE (UNLESS OTHERWISE SPECIFIED):" at 11408.23,5519.1 h60
  text "+/-" at 13778,5516.23 h60
  text "3" at 14017.2,5515.17 h60
  text "MIL" at 14133.46,5515.17 h60
  text "MATERIAL:" at 11333.46,5377.52 h60
  text "FR-4 High Tg" at 12319.9,5249 h60
  text "X" at 12175.46,5241.01 h60
  text "FR-408" at 11754.46,5236.49 h60
  text "OTHER" at 13242.46,5236.49 h60
  text "62 MIL (1.6mm) +/-10%" at 12074.56,5093.46 h60
  text "X" at 11954.46,5091.01 h60
  text "THICKNESS:" at 11408.23,5085.24 h60
  text "OTHER" at 13359.46,5085.24 h60
  text "TOLERANCE:" at 11408.23,4946.92 h60
  text "X" at 12256.46,4946.92 h60
  text "ANSI IPC-6012 TYPE 3 CLASS 2" at 12434.48,4946.92 h60
  text "OTHER +/-" at 12434.46,4802.73 h60
  text "BOW & TWIST:" at 11408.23,4657.54 h60
  text "X" at 12256.46,4657.54 h60
  text "ANSI IPC-6012 TYPE 3 CLASS 2" at 12434.48,4657.54 h60
  text "OTHER +/-" at 12434.46,4510.85 h60
  text "DRILLING:" at 11333.46,4380.23 h60
  text "NC_DRILL FILES" at 13094.46,4275.04 h60
  text "REFERENCE:" at 11408.23,4271.1 h60
  text "X" at 12065.46,4271.01 h60
  text "AS SHOWN" at 12243.46,4271.1 h60
  text "X" at 12966.46,4271.1 h60
  text "OTHER" at 13392.46,4128.85 h60
  text "PTH COPPER THICKNESS:" at 11407.91,4125.32 h60
  text "X" at 12547.14,4125.32 h60
  text "20-30 um" at 12675.14,4125.32 h60
  text "BOARD FINISH:" at 11333.46,3977.73 h60
  text "SILKSCREEN:" at 11488.68,3867.6 h60
  text "X" at 12446.46,3867.6 h60
  text "TOP" at 12563.46,3867.6 h60
  text "X" at 12956.46,3867.6 h60
  text "BOTTOM" at 13074.46,3867.6 h60
  text "SILKSCREEN COLOR:" at 11488.68,3712.41 h60
  text "X" at 12445.46,3712.41 h60
  text "WHITE" at 12563.46,3712.41 h60
  text "OTHER" at 13074.46,3712.41 h60
  text "X" at 12576.46,3568.96 h60
  text "GREEN" at 12694.46,3568.96 h60
  text "OTHER" at 13312.46,3568.96 h60
  text "SOLDER RESIST COLOR:" at 11488.68,3562.1 h60
  text "X" at 12576.46,3414.71 h60
  text "MATTE" at 12694.46,3414.71 h60
  text "SEMI-GLOSS" at 13312,3414.07 h60
  text "IMMERSION GOLD (ENIG)" at 12394.46,3241.94 h60
  text "ENEPIG" at 13732,3234.72 h60
  text "SURFACE FINISH:" at 11333.46,3233.72 h60
  text "X" at 12216.46,3233.72 h60
  text "IMM. TIN/SILVER OR EQUIV" at 11663,3096.4 h60
  text "OTHER" at 13094.46,3092.47 h60
  text "ARRAY/PANEL:" at 11333.46,2937.09 h60
  text "CUT AND TRIM PER M1 BOARD OUTLINE" at 12394.46,2928.87 h60
  text "N.C. ROUTE" at 12394.46,2792.9 h60
  text "X" at 13082.46,2792.9 h60
  text "V. SCORE" at 13260.46,2792.9 h60
  text "CERTIFICATION:" at 11333.46,2663.77 h60
  text "MATERIALS AND WORKMANSHIP FOR ALL PCBS" at 12058.46,2663.77 h60
  text "TO MEET OR EXCEED THE REQUIREMENTS OF:" at 12058.46,2569.71 h60
  text "X" at 11695.97,2441.08 h60
  text "ANSI IPC-A-600F CLASS ->" at 11823.96,2441.08 h60
  text "X" at 13471.97,2441.08 h60
  text "2" at 13581.96,2441.08 h60
  text "1" at 13266.96,2439.58 h60
  text "3" at 13935.96,2439.58 h60
  text "X" at 12507.97,2293.39 h60
  text "RoHS" at 12635.96,2293.39 h60
  text "OTHER" at 13280.36,2293.39 h60
  text "PER ORDER" at 13677.42,2293.39 h60
  text "ALL BOARDS MUST MEET OR EXCEED UL94-V0 REQUIREMENTS." at 11361,2139.57 h60
  text "PCB MUST BEAR THE UL94V-0 UL REGISTERED MATERIAL ID NUMBER" at 11361,2023.5 h60
  text "ADDITIONAL REQUIREMENTS:" at 11333.46,1854.08 h60
  text "MICROSECTION:" at 11408.23,1746.95 h60
  text "YES" at 12313.96,1746.95 h60
  text "REQUIRED" at 13175.46,1602.62 h60
  text "BARE BOARD ELEC. TEST:" at 11408.23,1599.76 h60
  text "NONE" at 12713.96,1599.76 h60
  text "X" at 13057.46,1599.76 h60
  text "PER ORDER" at 13767.46,1599.76 h60
  text "XX MIL VIAS REQUIRE NON-CONDUCTIVE FILL AND PLANARIZE" at 11576.38,1394.82 h59
  text "XX MIL VIAS REQUIRE CONDUCTIVE FILL AND PLANARIZE" at 11584.38,1290.84 h60
  text "OUTER XX MIL VIAS REQUIRE 50 OHM SINGLE-ENDED IMPEDANCE" at 11583.39,1127.46 h58
  text "LAYER 2 & 3 (INNER LAYERS) XX MIL WIDE, XX MIL SPACE / TRACES REQUIRE 100 OHM DIFFERENTIAL IMPEDANCE" at 11575.39,891.74 h60
  text ".Layer_Name" at 577,-858.49 h60
M11 Gerber Information:
  lines w10: -292,-930.17 6308,-930.17 ; -292,-726.83 6310,-726.83 ; -292,-523.5 -292,-1133.5 3713,-1133.5 6310,-1133.5 6310,-523.5 -291.5,-523.5 -291.5,-1133.5 1284,-1133.5 ; 2173,-1133.5 2173,-523.5 ; 3440,-726.83 3440,-523.5 ; 4280,-726.83 4280,-523.5 ; 4902,-1140 4902,-937.17
  text "ALL ARTWORK VIEWED FROM TOP SIDE" at -228.5,-655.67 h60
  text "BOARD #:" at 2248,-655.67 h60
  text ".PRJ_Number" at 2793.5,-655.67 h60
  text "REV:" at 3638,-655.67 h60
  text ".PCB_Rev" at 3929.5,-655.67 h60
  text "SVN REV:" at 4476,-655.67 h60
  text ".VersionControl_RevNumber" at 4982,-655.67 h60
  text "LAYER NAME =" at -228.5,-858.49 h60
  text "TID #:" at 2248,-859 h60
  text ".TID" at 2793.5,-859 h60
  text "PLOT NAME =" at -228.5,-1064.34 h60
  text ".plot_File_Name" at 577,-1064.34 h60
  text "GENERATED    :" at 2250,-1064.34 h60
  text ".Print_Date" at 3119.5,-1064.34 h60
  text ".Print_Time" at 3848.5,-1064.34 h60
  text "TEXAS INSTRUMENTS" at 5113,-1064.34 h60
M12 Stackup:
  drawing of 191 lines, arcs and shapes, not listed
  text "Layer" at 9797.84,7830 h60
  text "Name" at 10207.76,7830 h60
  text "Material" at 11137.5,7830 h60
  text "Thickness" at 11997.27,7830 h60
  text "Constant" at 12647.1,7830 h60
  text "Board Layer Stack" at 13216.96,7830 h60
  text "1" at 9797.84,7710 h60
  text "Top Overlay" at 10207.76,7710 h60
  text "2" at 9797.84,7590 h60
  text "Top Solder" at 10207.76,7590 h60
  text "Solder Resist" at 11137.5,7590 h60
  text "0.40mil" at 11997.27,7590 h60
  text "3.5" at 12647.1,7590 h60
  text "3" at 9797.84,7470 h60
  text "Top Layer" at 10207.76,7470 h60
  text "Copper" at 11137.5,7470 h60
  text "1.40mil" at 11997.27,7470 h60
  text "4" at 9797.84,7350 h60
  text "Dielectric1" at 10207.76,7350 h60
  text "FR-4" at 11137.5,7350 h60
  text "59.20mil" at 11997.27,7350 h60
  text "4.8" at 12647.1,7350 h60
  text "5" at 9797.84,7230 h60
  text "Bottom Layer" at 10207.76,7230 h60
  text "Copper" at 11137.5,7230 h60
  text "1.40mil" at 11997.27,7230 h60
  text "6" at 9797.84,7110 h60
  text "Bottom Solder" at 10207.76,7110 h60
  text "Solder Resist" at 11137.5,7110 h60
  text "0.40mil" at 11997.27,7110 h60
  text "3.5" at 12647.1,7110 h60
  text "7" at 9797.84,6990 h60
  text "Bottom Overlay" at 10207.76,6990 h60
  text ".Layer_Name" at 577,-858.49 h60
M13 Component Bodies Top:
  text ".Layer_Name" at 577,-858.49 h60
M14 Component Bodies Bottom:
  text ".Layer_Name" at 577,-858.49 h60
M15 Courtyards Top:
  text ".Layer_Name" at 577,-858.49 h60
M16 Courtyards Bottom:
  text ".Layer_Name" at 577,-858.49 h60
Drill Drawing:
  circle w10: c9454.68,3397.32 r27.63
  lines w10: 9427.05,3148.68 9454.68,3121.06 9482.31,3148.68 9454.68,3176.31 9427.05,3148.68 ; 9427.05,3245.38 9427.05,3259.19 9440.87,3273 9427.05,3286.82 9427.05,3300.63 9440.87,3300.63 9454.68,3286.82 9468.49,3300.63 9482.31,3300.63 9482.31,3286.82 9468.49,3273 9482.31,3259.19 9482.31,3245.38 9468.49,3245.38 9454.68,3259.19 9440.87,3245.38 9427.05,3245.38 ; 9427.05,3549.27 9482.31,3549.27 9454.68,3494.02 9427.05,3549.27 ; 9427.05,3618.34 9454.68,3632.15 9482.31,3618.34 9468.49,3645.96 9482.31,3673.59 9454.68,3659.78 9427.05,3673.59 9440.87,3645.96 9427.05,3618.34 ; 9427.05,3742.66 9482.31,3742.66 9482.31,3797.91 9427.05,3797.91 9427.05,3742.66
  lines w12: 9376.96,3083.76 12608.45,3083.76 ; 9376.96,3829.68 12608.45,3829.68 ; 9714.82,2959.44 9714.82,3954 ; 10046.83,2959.44 10046.83,3954 ; 10683.39,2959.44 10683.39,3954 ; 10942.53,2959.44 10942.53,3954 ; 11317.69,2959.44 11317.69,3954 ; 12042.02,2959.44 12042.02,3954 ; 9376.96,2959.44 12608.45,2959.44 12608.45,3954 9376.96,3954 9376.96,2959.44
  text "Symbol" at 9451.55,3866.98 h72
  text "Quantity" at 9752.12,3866.98 h72
  text "Finished Hole Size" at 10084.12,3866.98 h72
  text "Plated" at 10720.68,3866.98 h72
  text "Hole Type" at 10979.82,3866.98 h72
  text "Drill Layer Pair" at 11354.98,3866.98 h72
  text "Hole Tolerance" at 12079.31,3866.98 h72
  text "9" at 9752.12,3742.66 h60
  text "10.00mil (0.254mm)" at 10084.12,3742.66 h60
  text "PTH" at 10720.68,3742.66 h60
  text "Round" at 10979.82,3742.66 h60
  text "Top Layer - Bottom Layer" at 11354.98,3742.66 h60
  text "11" at 9752.12,3618.34 h60
  text "28.00mil (0.711mm)" at 10084.12,3618.34 h60
  text "PTH" at 10720.68,3618.34 h60
  text "Round" at 10979.82,3618.34 h60
  text "Top Layer - Bottom Layer" at 11354.98,3618.34 h60
  text "7" at 9752.12,3494.02 h60
  text "40.00mil (1.016mm)" at 10084.12,3494.02 h60
  text "PTH" at 10720.68,3494.02 h60
  text "Round" at 10979.82,3494.02 h60
  text "Top Layer - Bottom Layer" at 11354.98,3494.02 h60
  text "4" at 9752.12,3369.7 h60
  text "40.16mil (1.020mm)" at 10084.12,3369.7 h60
  text "PTH" at 10720.68,3369.7 h60
  text "Round" at 10979.82,3369.7 h60
  text "Top Layer - Bottom Layer" at 11354.98,3369.7 h60
  text "9" at 9752.12,3245.38 h60
  text "42.91mil (1.090mm)" at 10084.12,3245.38 h60
  text "PTH" at 10720.68,3245.38 h60
  text "Round" at 10979.82,3245.38 h60
  text "Top Layer - Bottom Layer" at 11354.98,3245.38 h60
  text "2" at 9752.12,3121.06 h60
  text "125.20mil (3.180mm)" at 10084.12,3121.06 h60
  text "PTH" at 10720.68,3121.06 h60
  text "Round" at 10979.82,3121.06 h60
  text "Top Layer - Bottom Layer" at 11354.98,3121.06 h60
  text "42 Total" at 9752.12,2996.74 h60
  text ".Layer_Name" at 577,-858.49 h60
M17 Embedded Cavity:
  text ".Layer_Name" at 577,-858.49 h60
M18 Embedded Assembly:
  text ".Layer_Name" at 577,-858.49 h60
M19 Embedded Keepout:
  text ".Layer_Name" at 577,-858.49 h60

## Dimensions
0,0 to 3800,0 on M2 Board Dimensions
0,-400 to 1000,-400 on M2 Board Dimensions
